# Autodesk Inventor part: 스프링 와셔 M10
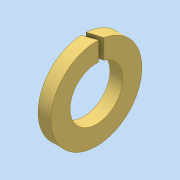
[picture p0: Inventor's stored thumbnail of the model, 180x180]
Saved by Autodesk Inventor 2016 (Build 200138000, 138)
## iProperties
Created: 2024-08
Part Number: 스프링 와셔 M10
Material: 일반
Description: 스프링 잠금 와셔
Document SubType Name: Modeling
Designer: pc-7
Density: 1 g/cm^3
Appearance: 기본값
Author: jhkim
Sending System: Autodesk Inventor 2025
Preprocessor: ST-DEVELOPER v20
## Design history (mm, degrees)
node "스프링 와셔 M101"
node "솔리드1"
body "Solid1"
